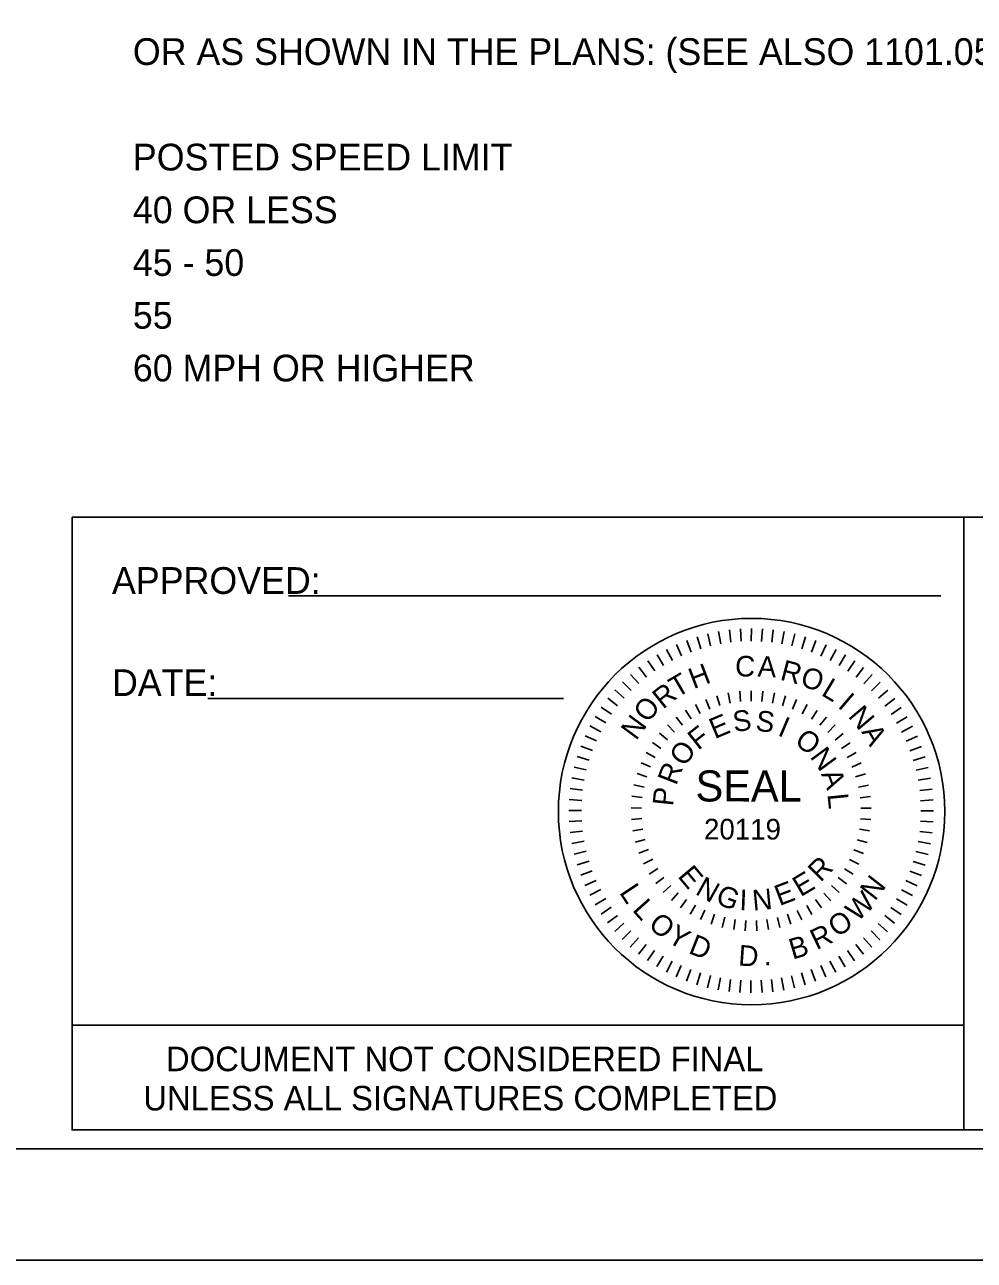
# Model space of a CAD drawing. Extents: x 762655 to 770567, y 650864 to 655190.
# Drawn here: x 763752.1 to 763965.1, y 652778.8 to 653056 of the extents above; entities that cross this region are included whole.
import ezdxf

# ---------------------------------------------------------------- set-up
doc = ezdxf.new("R2010")
doc.units = 0
for name, color, linetype in [('Default', 7, 'Continuous'), ('DEV BORDER CELL', 7, 'Continuous'), ('DEV TRANSPORTATION OPERATIONS PLAN SHEET', 7, 'Continuous'), ('Sheet Plot Border Outside CELL', 7, 'Continuous'), ('Sheet Sticker Exception Certification CELL', 7, 'Continuous')]:
    doc.layers.add(name, color=color, linetype=linetype)

msp = doc.modelspace()

# ---------------------------------------------------------------- linework, layer by layer
at = {"layer": 'Default'}
for p, q in [((763907.68, 652919.82), (763908.18, 652917.08)), ((763910.12, 652920.18), (763910.45, 652917.42)), ((763912.58, 652920.41), (763912.74, 652917.63)), ((763915.05, 652920.48), (763915.04, 652917.69)), ((763917.52, 652920.4), (763917.35, 652917.62)), ((763919.97, 652920.17), (763919.64, 652917.41)), ((763922.41, 652919.8), (763921.91, 652917.06)), ((763898.27, 652916.89), (763899.41, 652914.35)), ((763900.55, 652917.84), (763901.54, 652915.23)), ((763902.88, 652918.64), (763903.71, 652915.98)), ((763905.27, 652919.3), (763905.92, 652916.6)), ((763924.83, 652919.28), (763924.16, 652916.58)), ((763927.21, 652918.62), (763926.38, 652915.95)), ((763929.54, 652917.81), (763928.55, 652915.2)), ((763931.82, 652916.86), (763930.67, 652914.32)), ((763893.89, 652914.6), (763895.33, 652912.22)), ((763896.05, 652915.82), (763897.34, 652913.35)), ((763934.04, 652915.78), (763932.74, 652913.31)), ((763936.19, 652914.56), (763934.74, 652912.18)), ((763889.83, 652911.8), (763891.55, 652909.61)), ((763891.82, 652913.26), (763893.4, 652910.97)), ((763938.26, 652913.22), (763936.68, 652910.93)), ((763940.24, 652911.76), (763938.53, 652909.57)), ((763886.13, 652908.53), (763888.1, 652906.56)), ((763887.93, 652910.22), (763889.78, 652908.14)), ((763942.14, 652910.17), (763940.29, 652908.09)), ((763943.94, 652908.48), (763941.97, 652906.51)), ((763884.44, 652906.74), (763886.52, 652904.89)), ((763909.86, 652906.05), (763910.3, 652903.77)), ((763912.43, 652906.42), (763912.65, 652904.11)), ((763915.03, 652906.54), (763915.03, 652904.22)), ((763915.03, 652904.22), (763915.03, 652906.54)), ((763917.64, 652906.41), (763917.41, 652904.11)), ((763920.21, 652906.04), (763919.76, 652903.76)), ((763945.63, 652906.68), (763943.54, 652904.84)), ((763881.39, 652902.86), (763883.68, 652901.27)), ((763882.85, 652904.84), (763885.05, 652903.12)), ((763902.51, 652903.47), (763903.59, 652901.41)), ((763904.87, 652904.57), (763905.75, 652902.41)), ((763907.33, 652905.43), (763907.99, 652903.2)), ((763922.73, 652905.41), (763922.07, 652903.19)), ((763925.19, 652904.55), (763924.31, 652902.4)), ((763927.55, 652903.45), (763926.47, 652901.39)), ((763947.21, 652904.78), (763945.01, 652903.07)), ((763880.05, 652900.78), (763882.43, 652899.34)), ((763898.16, 652900.62), (763899.61, 652898.81)), ((763900.26, 652902.15), (763901.54, 652900.21)), ((763929.79, 652902.13), (763928.52, 652900.18)), ((763931.9, 652900.59), (763930.44, 652898.78)), ((763948.67, 652902.79), (763946.38, 652901.21)), ((763950.01, 652900.72), (763947.62, 652899.28)), ((763878.83, 652898.63), (763881.3, 652897.34)), ((763896.21, 652898.9), (763897.83, 652897.23)), ((763933.84, 652898.86), (763932.22, 652897.2)), ((763951.22, 652898.57), (763948.75, 652897.27)), ((763877.75, 652896.41), (763880.29, 652895.27)), ((763892.85, 652894.93), (763894.76, 652893.6)), ((763894.43, 652896.99), (763896.21, 652895.5)), ((763935.61, 652896.96), (763933.84, 652895.46)), ((763937.2, 652894.89), (763935.28, 652893.57)), ((763952.3, 652896.34), (763949.76, 652895.21)), ((763875.99, 652891.8), (763878.66, 652890.97)), ((763876.8, 652894.13), (763879.41, 652893.14)), ((763891.48, 652892.72), (763893.5, 652891.58)), ((763938.56, 652892.68), (763936.54, 652891.54)), ((763953.24, 652894.06), (763950.63, 652893.07)), ((763875.33, 652889.42), (763878.03, 652888.76)), ((763890.32, 652890.38), (763892.45, 652889.46)), ((763939.72, 652890.34), (763937.59, 652889.41)), ((763954.05, 652891.73), (763951.38, 652890.9)), ((763954.71, 652889.35), (763952, 652888.69)), ((763874.81, 652887.01), (763877.55, 652886.51)), ((763889.4, 652887.95), (763891.61, 652887.23)), ((763940.64, 652887.9), (763938.43, 652887.19)), ((763955.22, 652886.93), (763952.48, 652886.44)), ((763874.44, 652884.57), (763877.2, 652884.23)), ((763888.71, 652885.44), (763890.98, 652884.94)), ((763941.32, 652885.39), (763939.05, 652884.89)), ((763955.59, 652884.49), (763952.83, 652884.16)), ((763874.21, 652882.11), (763876.99, 652881.94)), ((763888.27, 652882.87), (763890.57, 652882.6)), ((763941.76, 652882.82), (763939.45, 652882.55)), ((763955.81, 652882.04), (763953.03, 652881.87)), ((763874.13, 652879.64), (763876.92, 652879.64)), ((763888.08, 652880.28), (763890.4, 652880.22)), ((763941.94, 652880.23), (763939.62, 652880.17)), ((763955.88, 652879.57), (763953.1, 652879.57)), ((763874.21, 652877.17), (763876.99, 652877.34)), ((763888.14, 652877.68), (763890.45, 652877.84)), ((763888.45, 652875.09), (763890.74, 652875.48)), ((763939.28, 652875.52), (763941.58, 652875.13)), ((763941.88, 652877.63), (763939.56, 652877.8)), ((763955.81, 652877.1), (763953.03, 652877.27)), ((763874.43, 652874.71), (763877.19, 652875.04)), ((763874.79, 652872.27), (763877.53, 652872.77)), ((763889.01, 652872.55), (763891.25, 652873.16)), ((763941, 652872.5), (763938.76, 652873.11)), ((763955.21, 652872.2), (763952.47, 652872.7)), ((763955.58, 652874.64), (763952.82, 652874.97)), ((763875.31, 652869.86), (763878.02, 652870.52)), ((763889.81, 652870.07), (763891.98, 652870.89)), ((763940.19, 652870.02), (763938.02, 652870.85)), ((763954.69, 652869.79), (763951.98, 652870.45)), ((763875.97, 652867.48), (763878.64, 652868.3)), ((763890.85, 652867.69), (763892.93, 652868.72)), ((763939.14, 652867.64), (763937.07, 652868.67)), ((763954.02, 652867.4), (763951.36, 652868.24)), ((763876.77, 652865.14), (763879.38, 652866.13)), ((763892.11, 652865.41), (763894.08, 652866.63)), ((763893.59, 652863.26), (763895.43, 652864.67)), ((763936.4, 652863.22), (763934.55, 652864.64)), ((763937.88, 652865.37), (763935.91, 652866.59)), ((763953.22, 652865.07), (763950.61, 652866.07)), ((763877.72, 652862.86), (763880.26, 652864)), ((763878.8, 652860.64), (763881.27, 652861.93)), ((763895.27, 652861.28), (763896.96, 652862.85)), ((763934.72, 652861.24), (763933.02, 652862.82)), ((763951.19, 652860.57), (763948.72, 652861.87)), ((763952.26, 652862.8), (763949.73, 652863.94)), ((763880.01, 652858.49), (763882.39, 652859.93)), ((763897.12, 652859.46), (763898.67, 652861.19)), ((763899.15, 652857.82), (763900.52, 652859.7)), ((763930.82, 652857.8), (763929.46, 652859.67)), ((763932.86, 652859.42), (763931.32, 652861.16)), ((763949.97, 652858.42), (763947.59, 652859.87)), ((763881.35, 652856.41), (763883.64, 652857.99)), ((763882.81, 652854.43), (763885, 652856.14)), ((763901.33, 652856.4), (763902.51, 652858.4)), ((763903.63, 652855.18), (763904.62, 652857.29)), ((763906.05, 652854.2), (763906.82, 652856.39)), ((763923.92, 652854.18), (763923.15, 652856.38)), ((763926.34, 652855.16), (763925.36, 652857.27)), ((763928.65, 652856.37), (763927.47, 652858.37)), ((763947.16, 652854.37), (763944.97, 652856.08)), ((763948.63, 652856.35), (763946.34, 652857.94)), ((763884.39, 652852.53), (763886.47, 652854.37)), ((763909.08, 652855.71), (763908.52, 652853.45)), ((763911.09, 652852.95), (763911.43, 652855.25)), ((763913.68, 652852.69), (763913.79, 652855.01)), ((763916.28, 652852.69), (763916.18, 652855.01)), ((763918.88, 652852.94), (763918.54, 652855.24)), ((763921.43, 652853.44), (763920.88, 652855.7)), ((763945.58, 652852.47), (763943.5, 652854.32)), ((763886.08, 652850.73), (763888.05, 652852.69)), ((763887.87, 652849.03), (763889.72, 652851.12)), ((763942.09, 652848.98), (763940.24, 652851.07)), ((763943.88, 652850.67), (763941.92, 652852.65)), ((763889.77, 652847.45), (763891.49, 652849.64)), ((763891.76, 652845.99), (763893.34, 652848.27)), ((763938.2, 652845.94), (763936.62, 652848.23)), ((763940.19, 652847.4), (763938.47, 652849.6)), ((763893.83, 652844.64), (763895.27, 652847.02)), ((763895.98, 652843.43), (763897.28, 652845.89)), ((763898.2, 652842.35), (763899.34, 652844.88)), ((763931.75, 652842.32), (763930.61, 652844.86)), ((763933.97, 652843.39), (763932.68, 652845.86)), ((763936.12, 652844.6), (763934.68, 652846.99)), ((763900.48, 652841.4), (763901.47, 652844)), ((763902.81, 652840.59), (763903.64, 652843.25)), ((763905.19, 652839.92), (763905.86, 652842.63)), ((763907.6, 652839.4), (763908.11, 652842.14)), ((763922.34, 652839.39), (763921.84, 652842.13)), ((763924.75, 652839.91), (763924.09, 652842.61)), ((763927.14, 652840.56), (763926.31, 652843.23)), ((763929.47, 652841.37), (763928.48, 652843.98)), ((763910.04, 652839.03), (763910.38, 652841.79)), ((763912.5, 652838.81), (763912.67, 652841.59)), ((763914.97, 652838.73), (763914.97, 652841.51)), ((763917.44, 652838.8), (763917.28, 652841.58)), ((763919.9, 652839.02), (763919.57, 652841.79))]:
    msp.add_line(p, q, dxfattribs=at)
at = {"layer": 'DEV BORDER CELL'}
for p, q in [((763811.21, 652927.84), (763957.55, 652927.84)), ((763962.7, 652922.02), (763962.7, 652808.02)), ((763793.1, 652904.77), (763872.89, 652904.77))]:
    msp.add_line(p, q, dxfattribs=at)
for points in [[(763762.66, 652945.52), (763962.7, 652945.52), (763962.7, 652808.02), (763762.66, 652808.02)], [(763962.7, 652945.52), (764076.7, 652945.52), (764076.7, 652808.02), (763962.7, 652808.02)]]:
    msp.add_lwpolyline(points, close=True, dxfattribs=at)
msp.add_circle((763915.1, 652879.43), 43.34, dxfattribs=at)
at = {"layer": 'DEV TRANSPORTATION OPERATIONS PLAN SHEET'}
msp.add_lwpolyline([(764317.85, 653853.76), (762817.85, 653853.76), (762817.85, 652803.75), (764317.85, 652803.75)], close=True, dxfattribs=at)
at = {"layer": 'Sheet Plot Border Outside CELL'}
msp.add_lwpolyline([(762654.85, 652778.75), (764342.85, 652778.75), (764342.85, 653878.75), (762654.85, 653878.75)], close=True, dxfattribs=at)
at = {"layer": 'Sheet Sticker Exception Certification CELL'}
for p, q in [((763762.66, 652808.02), (763762.66, 652831.52)), ((763762.66, 652831.52), (763962.7, 652831.52)), ((763962.7, 652831.51), (763962.7, 652808.01)), ((763962.7, 652808.02), (763762.66, 652808.02))]:
    msp.add_line(p, q, dxfattribs=at)

# ---------------------------------------------------------------- texts
at = {"layer": 'Default'}
for s, p in [('           OR AS SHOWN IN THE PLANS: (SEE ALSO 1101.05)', (763751.79, 653046.94)), ('           POSTED SPEED LIMIT', (763751.79, 653023.27)), ('           40 OR LESS', (763751.79, 653011.44)), ('           45 - 50', (763751.79, 652999.61)), ('           55', (763751.79, 652987.77)), ('           60 MPH OR HIGHER', (763751.79, 652975.94))]:
    msp.add_text(s, height=6, dxfattribs=at).set_placement(p)
for s, height, rotation, p in [('C', 4.64, 357.3039, (763911.32, 652909.84)), ('A', 4.64, 357.3039, (763916.39, 652909.75)), ('H', 4.64, 21.0146, (763902.09, 652906.87)), ('R', 4.64, 345.2946, (763921.31, 652909.06)), ('O', 4.64, 342.2378, (763925.8, 652907.72)), ('T', 4.64, 30.4466, (763898.35, 652904.85)), ('L', 4.64, 329.1015, (763930.52, 652905.65)), ('R', 4.64, 38.6075, (763895.23, 652902.26)), ('I', 4.64, 319.5261, (763934.26, 652902.95)), ('O', 4.64, 51.6643, (763891.86, 652899.14)), ('N', 4.64, 310.2316, (763936.59, 652900.76)), ('N', 4.64, 53.6237, (763889.19, 652895.22)), ('E', 4.64, 22.8914, (763906.84, 652895.66)), ('S', 4.64, 7.5951, (763911.2, 652897.25)), ('S', 4.64, 352.2989, (763915.83, 652897.63)), ('I', 4.64, 337.0026, (763920.76, 652896.62)), ('F', 4.64, 38.1876, (763903.12, 652893.04)), ('O', 4.64, 321.7064, (763924.5, 652894.81)), ('A', 4.64, 300.4641, (763939.64, 652897.33)), ('O', 4.64, 53.4838, (763900.03, 652889.3)), ('N', 4.64, 306.4101, (763928.07, 652891.7)), ('R', 4.64, 68.7801, (763898.19, 652885.13)), ('SEAL', 6.965, 359.947, (763902.53, 652881.7)), ('A', 4.64, 291.1139, (763930.62, 652887.9)), ('P', 4.64, 84.0763, (763897.49, 652880.53)), ('L', 4.64, 275.8176, (763932.11, 652883.31)), ('20119', 4.64, 359.947, (763904.43, 652873.17)), ('E', 4.64, 310.0171, (763898.36, 652864.88)), ('R', 4.64, 44.5119, (763930.54, 652863.42)), ('N', 4.64, 330.8721, (763902.26, 652861.01)), ('E', 4.64, 30.7408, (763926.11, 652860.19)), ('N', 4.64, 52.154, (763942.75, 652859.21)), ('L', 4.64, 303.882, (763885.32, 652861.26)), ('G', 4.64, 339.6384, (763906.8, 652858.83)), ('I', 4.64, 357.7332, (763912.32, 652857.34)), ('N', 4.64, 5.3628, (763915.47, 652857.18)), ('E', 4.64, 20.7549, (763921.35, 652858.21)), ('W', 4.64, 43.2714, (763938.85, 652854.55)), ('L', 4.64, 311.9538, (763888.19, 652857.27)), ('O', 4.64, 320.5966, (763891.71, 652853.61)), ('O', 4.64, 34.3888, (763934.29, 652851.07)), ('Y', 4.64, 329.2691, (763895.93, 652850.37)), ('R', 4.64, 25.5662, (763929.68, 652848.3)), ('D', 4.64, 338.2416, (763900.75, 652847.74)), ('B', 4.64, 16.5636, (763924.31, 652846.2)), ('D', 4.64, 356.0369, (763912.03, 652844.91)), ('.', 4.64, 3.7793, (763917.89, 652844.87))]:
    msp.add_text(s, height=height, rotation=rotation, dxfattribs=at).set_placement(p)
at = {"layer": 'DEV BORDER CELL'}
for s, p in [('APPROVED:  ', (763771.63, 652928.27)), ('DATE:  ', (763771.63, 652905.36))]:
    msp.add_text(s, height=6, dxfattribs=at).set_placement(p)
at = {"layer": 'Sheet Sticker Exception Certification CELL'}
for s, p in [('DOCUMENT NOT CONSIDERED FINAL', (763783.74, 652821.18)), ('UNLESS ALL SIGNATURES COMPLETED', (763778.66, 652812.38))]:
    msp.add_text(s, height=5.5, dxfattribs=at).set_placement(p)

doc.saveas('drawing.dxf')
